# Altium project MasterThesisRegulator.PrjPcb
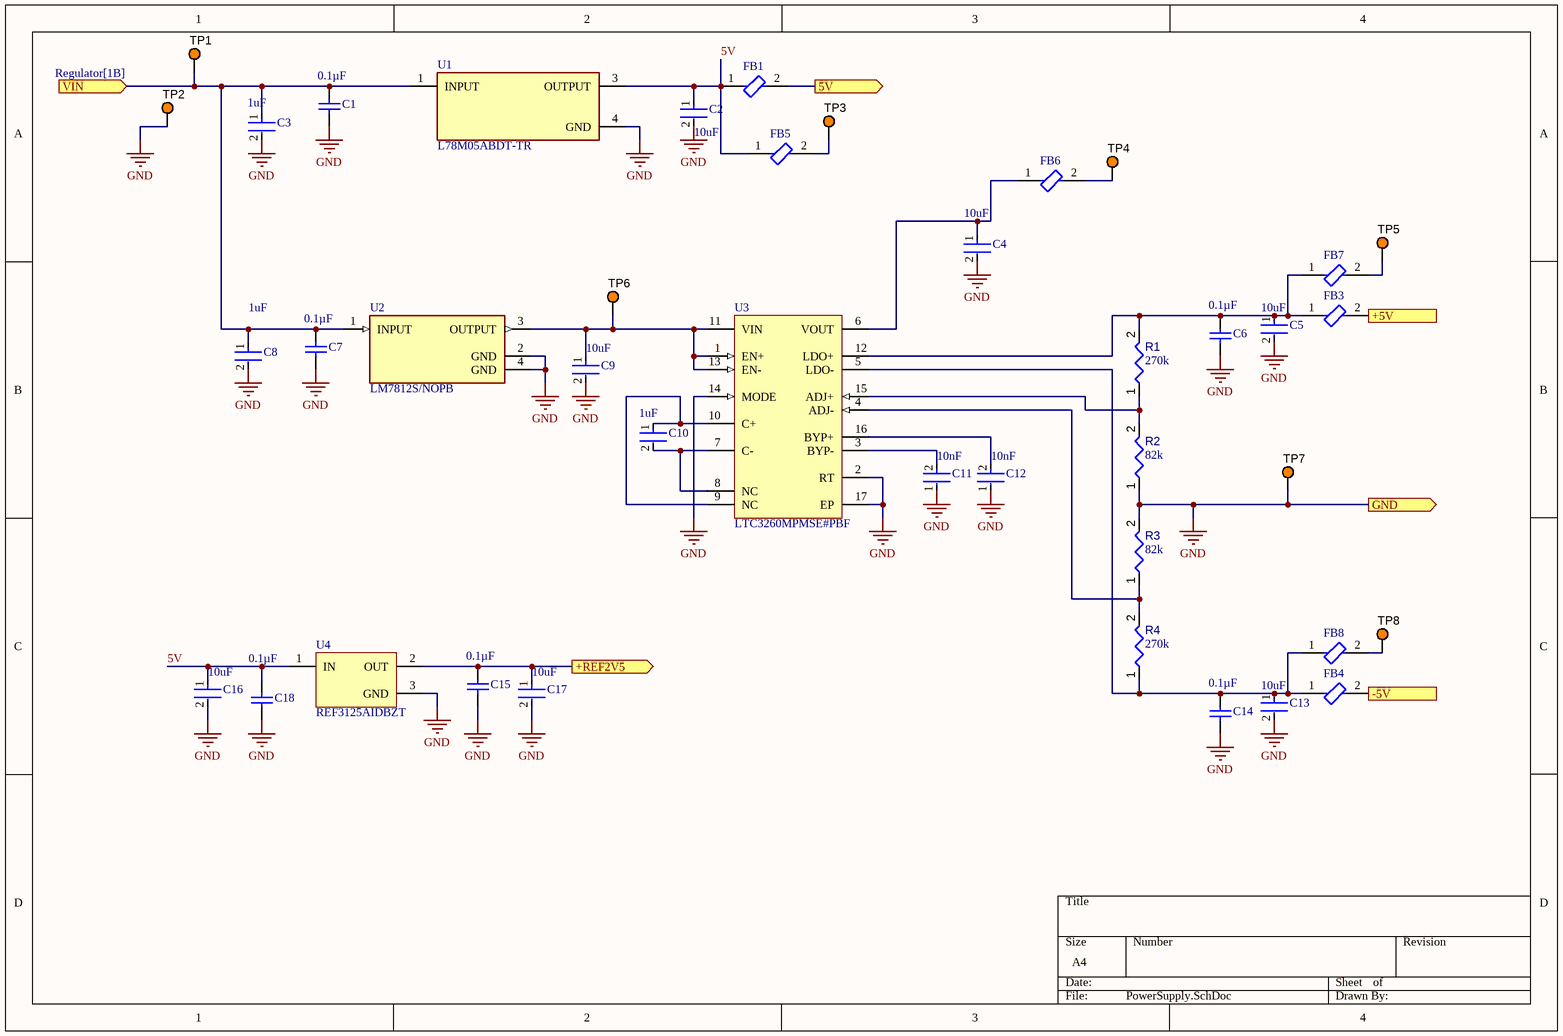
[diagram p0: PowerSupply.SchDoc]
4 sheets, 186 parts. Net scope: flat (ports and power ports of the same name join across sheets).
Board file: PCB1.PcbDoc
Sheets:
  PowerSupply.SchDoc
  Regulator.SchDoc
  ILoopAnd0.05V.SchDoc
  Support.SchDoc

## Sheet PowerSupply.SchDoc
size A4; SheetNumber: 1; SheetTotal: 5

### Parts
C1  Capacitance: 0.1µF  [SAMS-C0603-2_M]  (hidden comment: CL10B104KB8NNNC)
C2  value 10uF  [FP-CL31B106KBHNNNE-MFG]  (hidden comment: CL31B106KBHNNNE)
C3  Capacitance: 1uF  [FP-CL21-IPC_C]  (hidden comment: CL21B105KBFNNNG)
C4  value 10uF  [FP-CL31B106KBHNNNE-MFG]  (hidden comment: CL31B106KBHNNNE)
C5  value 10uF  [FP-CL31B106KBHNNNE-MFG]  (hidden comment: CL31B106KBHNNNE)
C6  Capacitance: 0.1µF  [SAMS-C0603-2_M]  (hidden comment: CL10B104KB8NNNC)
C7  Capacitance: 0.1µF  [SAMS-C0603-2_M]  (hidden comment: CL10B104KB8NNNC)
C8  Capacitance: 1uF  [FP-CL21-IPC_C]  (hidden comment: CL21B105KBFNNNG)
C9  value 10uF  [FP-CL31B106KBHNNNE-MFG]  (hidden comment: CL31B106KBHNNNE)
C10  Capacitance: 1uF  [FP-0603-L_1_6_0_15-W_0_8-IPC_C]  (hidden comment: UMK107AB7105KA-T)
C11  Capacitance: 10nF  [FP-C1608-080-0_1-MFG]  (hidden comment: C1608X7R1H103M080AA)
C12  Capacitance: 10nF  [FP-C1608-080-0_1-MFG]  (hidden comment: C1608X7R1H103M080AA)
C13  value 10uF  [FP-CL31B106KBHNNNE-MFG]  (hidden comment: CL31B106KBHNNNE)
C14  Capacitance: 0.1µF  [SAMS-C0603-2_M]  (hidden comment: CL10B104KB8NNNC)
C15  Capacitance: 0.1µF  [SAMS-C0603-2_M]  (hidden comment: CL10B104KB8NNNC)
C16  value 10uF  [FP-CL31B106KBHNNNE-MFG]  (hidden comment: CL31B106KBHNNNE)
C17  value 10uF  [FP-CL31B106KBHNNNE-MFG]  (hidden comment: CL31B106KBHNNNE)
C18  Capacitance: 0.1µF  [SAMS-C0603-2_M]  (hidden comment: CL10B104KB8NNNC)
FB1  BLM18PG600SH1D  [FP-BLM18-0_15-t0_8-IPC_C]  (value not drawn)
FB3  BLM18PG600SH1D  [FP-BLM18-0_15-t0_8-IPC_C]  (value not drawn)
FB4  BLM18PG600SH1D  [FP-BLM18-0_15-t0_8-IPC_C]  (value not drawn)
FB5  BLM18PG600SH1D  [FP-BLM18-0_15-t0_8-IPC_C]  (value not drawn)
FB6  BLM18PG600SH1D  [FP-BLM18-0_15-t0_8-IPC_C]  (value not drawn)
FB7  BLM18PG600SH1D  [FP-BLM18-0_15-t0_8-IPC_C]  (value not drawn)
FB8  BLM18PG600SH1D  [FP-BLM18-0_15-t0_8-IPC_C]  (value not drawn)
R1  value 270k  [RESC0603(1608)_L]  (hidden comment: SFR03EZPJ274)
R2  value 82k  [RESC0603(1608)_L]  (hidden comment: SFR03EZPJ823)
R3  value 82k  [RESC0603(1608)_L]  (hidden comment: SFR03EZPJ823)
R4  value 270k  [RESC0603(1608)_L]  (hidden comment: SFR03EZPJ274)
TP1  5003  [KSTN-5003]  (value not drawn)
TP2  5003  [KSTN-5003]  (value not drawn)
TP3  5003  [KSTN-5003]  (value not drawn)
TP4  5003  [KSTN-5003]  (value not drawn)
TP5  5003  [KSTN-5003]  (value not drawn)
TP6  5003  [KSTN-5003]  (value not drawn)
TP7  5003  [KSTN-5003]  (value not drawn)
TP8  5003  [KSTN-5003]  (value not drawn)
U1  L78M05ABDT-TR  [FP-L78M05ABDT-TR-MFG]
U2  LM7812S/NOPB  [FP-KTT0003B-MFG]
U3  LTC3260MPMSE#PBF  [LT-MSE-16-EDP_N]
U4  REF3125AIDBZT  [DBZ0003A_M]

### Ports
5V (out, see Regulator[2D], Support[1A]), +5V (out, see ILoopAnd0.05V[2C], Regulator[2D], Support[1A]), +REF2V5 (out, see ILoopAnd0.05V[2A], Regulator[6B]), -5V (out, see ILoopAnd0.05V[2C], Regulator[2D], Support[1A]), GND (out, see ILoopAnd0.05V[2C], Regulator[2C], Support[1A]), VIN (in, see Regulator[1B])

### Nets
+5: FB1.2 FB3.2 ; port 5V, port +5V
-5: FB4.2 ; port -5V
GND: C1.1 C2.2 C3.2 C4.2 C5.2 C6.1 C7.1 C8.2 C9.2 C11.1 C12.1 C13.2 C14.1 C15.1 C16.2 C17.2 C18.1 R2.1 R3.2 TP2.1 TP7.1 U1.4(GND) U2.2(GND) U2.4(GND) U3.2(RT) U3.14(MODE) U3.17(EP) U4.3(GND) ; port GND
5V: C2.1 C16.1 C18.2 FB1.1 FB5.1 U1.3(OUTPUT) U4.1(IN)
+REF2V5: C15.2 C17.1 U4.2(OUT) ; port +REF2V5
NetC1_2: C1.2 C3.1 C7.2 C8.1 TP1.1 U1.1(INPUT) U2.1(INPUT) ; port VIN
NetC4_1: C4.1 FB6.1 U3.6(VOUT)
NetC5_1: C5.1 C6.2 FB3.1 FB7.1 R1.2 U3.12(LDO+)
NetC9_1: C9.1 TP6.1 U2.3(OUTPUT) U3.1(EN+) U3.11(VIN) U3.13(EN-)
NetC10_1: C10.1 U3.9(NC) U3.10(C+)
NetC10_2: C10.2 U3.7(C-) U3.8(NC)
NetC11_2: C11.2 U3.3(BYP-)
NetC12_2: C12.2 U3.16(BYP+)
NetC13_1: C13.1 C14.2 FB4.1 FB8.1 R4.1 U3.5(LDO-)
NetFB5_2: FB5.2 TP3.1
NetFB6_2: FB6.2 TP4.1
NetFB7_2: FB7.2 TP5.1
NetFB8_2: FB8.2 TP8.1
NetR1_1: R1.1 R2.2 U3.15(ADJ+)
NetR3_1: R3.1 R4.2 U3.4(ADJ-)

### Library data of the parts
C1 C6 C7 C14 C15 C18 = CMP-2000-05332-1: Multi-layer Ceramic Capacitor, -55 to 125 degC, 2-Pin SMD (0603), RoHS, Tape and Reel; Manufacturer: Samsung Electro-Mechanics; Rated Voltage: 50V; Dielectric: X7R; Tolerance (%): ±10%
C2 C4 C5 C9 C13 C16 C17 = CMP-2000-07530-2: CAP CER 10UF 50V X7R 1206; Manufacturer: Samsung; Tolerance: 10%; Material: Ceramic; Temperature Coefficient: 15%
C3 C8 = CMP-13271-001433-1: CL21 Series 0805 1uF 50V ±10% Tolerance X7R Multilayer Ceramic Chip Capacitor
C10 = CMP-2000-07531-4: Ceramic Capacitor General Use 1uF ±10% 50V X7R 0603
C11 C12 = CMP-08246-006703-1: Multilayer Ceramic Capacitors 10nF ±20% 50V X7R SMD 0603
FB1 FB3-FB8 = CMP-06046-002563-1: Chip Ferrite Bead, 0603, 60Ω @ 100MHz, 0.1Ω, , 1A; Max Current Rating: 500mA; Impedance: 60R; DC Resistance (DCR): 100mR; Number of Circuits: 1; Material: Steel; Tolerance: 25%; Shielding: Unshielded
R1 R4 = CMP-009-00069-1: Manufacturer: Rohm; Power: 0.1W; Tolerance: 5%
R2 R3 = CMP-009-00069-1: Power: 0.1W; Tolerance: 5%
TP1-TP8 = CMP-002-00037-1: Test Point, Orange, Height 4.6 mm, Tail Length 3 mm, 1-Pin THD, RoHS; Manufacturer: Keystone
U1 = CMP-0244-00177-2: IC REG LINEAR 5V 500MA DPAK; Polarity: Positive; Accuracy: 2%; Max Input Voltage: 35V; Tolerance: 4%; Power Supply Rejection Ratio (PSRR): 62dB; Dropout Voltage: 2V; Output Type: Fixed; Number of Regulators: 1; Min Input Voltage: 10V; Quiescent Current: 6mA
U2 = CMP-04917-000197-1: IC REG LINEAR 12V 1.5A; Quiescent Current: 8mA; Dropout Voltage: 2V
U3 = CMP-0475-00263-1: Low Noise Dual Supply Inverting Charge Pump, 4.5 to 32 V Vin, Adjustable Vout, 16-pin SOP (MSE-16-EDP), -50 to 150 degC, Pb-Free; Manufacturer: Linear Technology; Isupply(mA): 0.1; Ishutdown(uA): 2; Vin Min(V): 4.5; Voutput: Adj; Max Iout(mA): 100; Vin Max(V): 32; Frequency(kHz): 500
U4 = CMP-0367-00203-2: 20 ppm / degC Max, 100 uA Series Voltage Reference, -40 to 125 degC, 3-pin SOT-23 (DBZ), Green (RoHS & no Sb/Br); Manufacturer: Texas Instruments; Temp Coeff(Typ)(ppm/ degree C): 10; Temp Coeff(Max)(ppm/ degree C): 20; VI(Max)(V): 5.5; Iq(Max)(uA): 100; VO(V): 2.5; Initial Accuracy @ 25/deg C(%): 0.2; Rating: Catalog; VI(Min)(V): 2.55

## Sheet Regulator.SchDoc
size A3; SheetNumber: 2; SheetTotal: 5
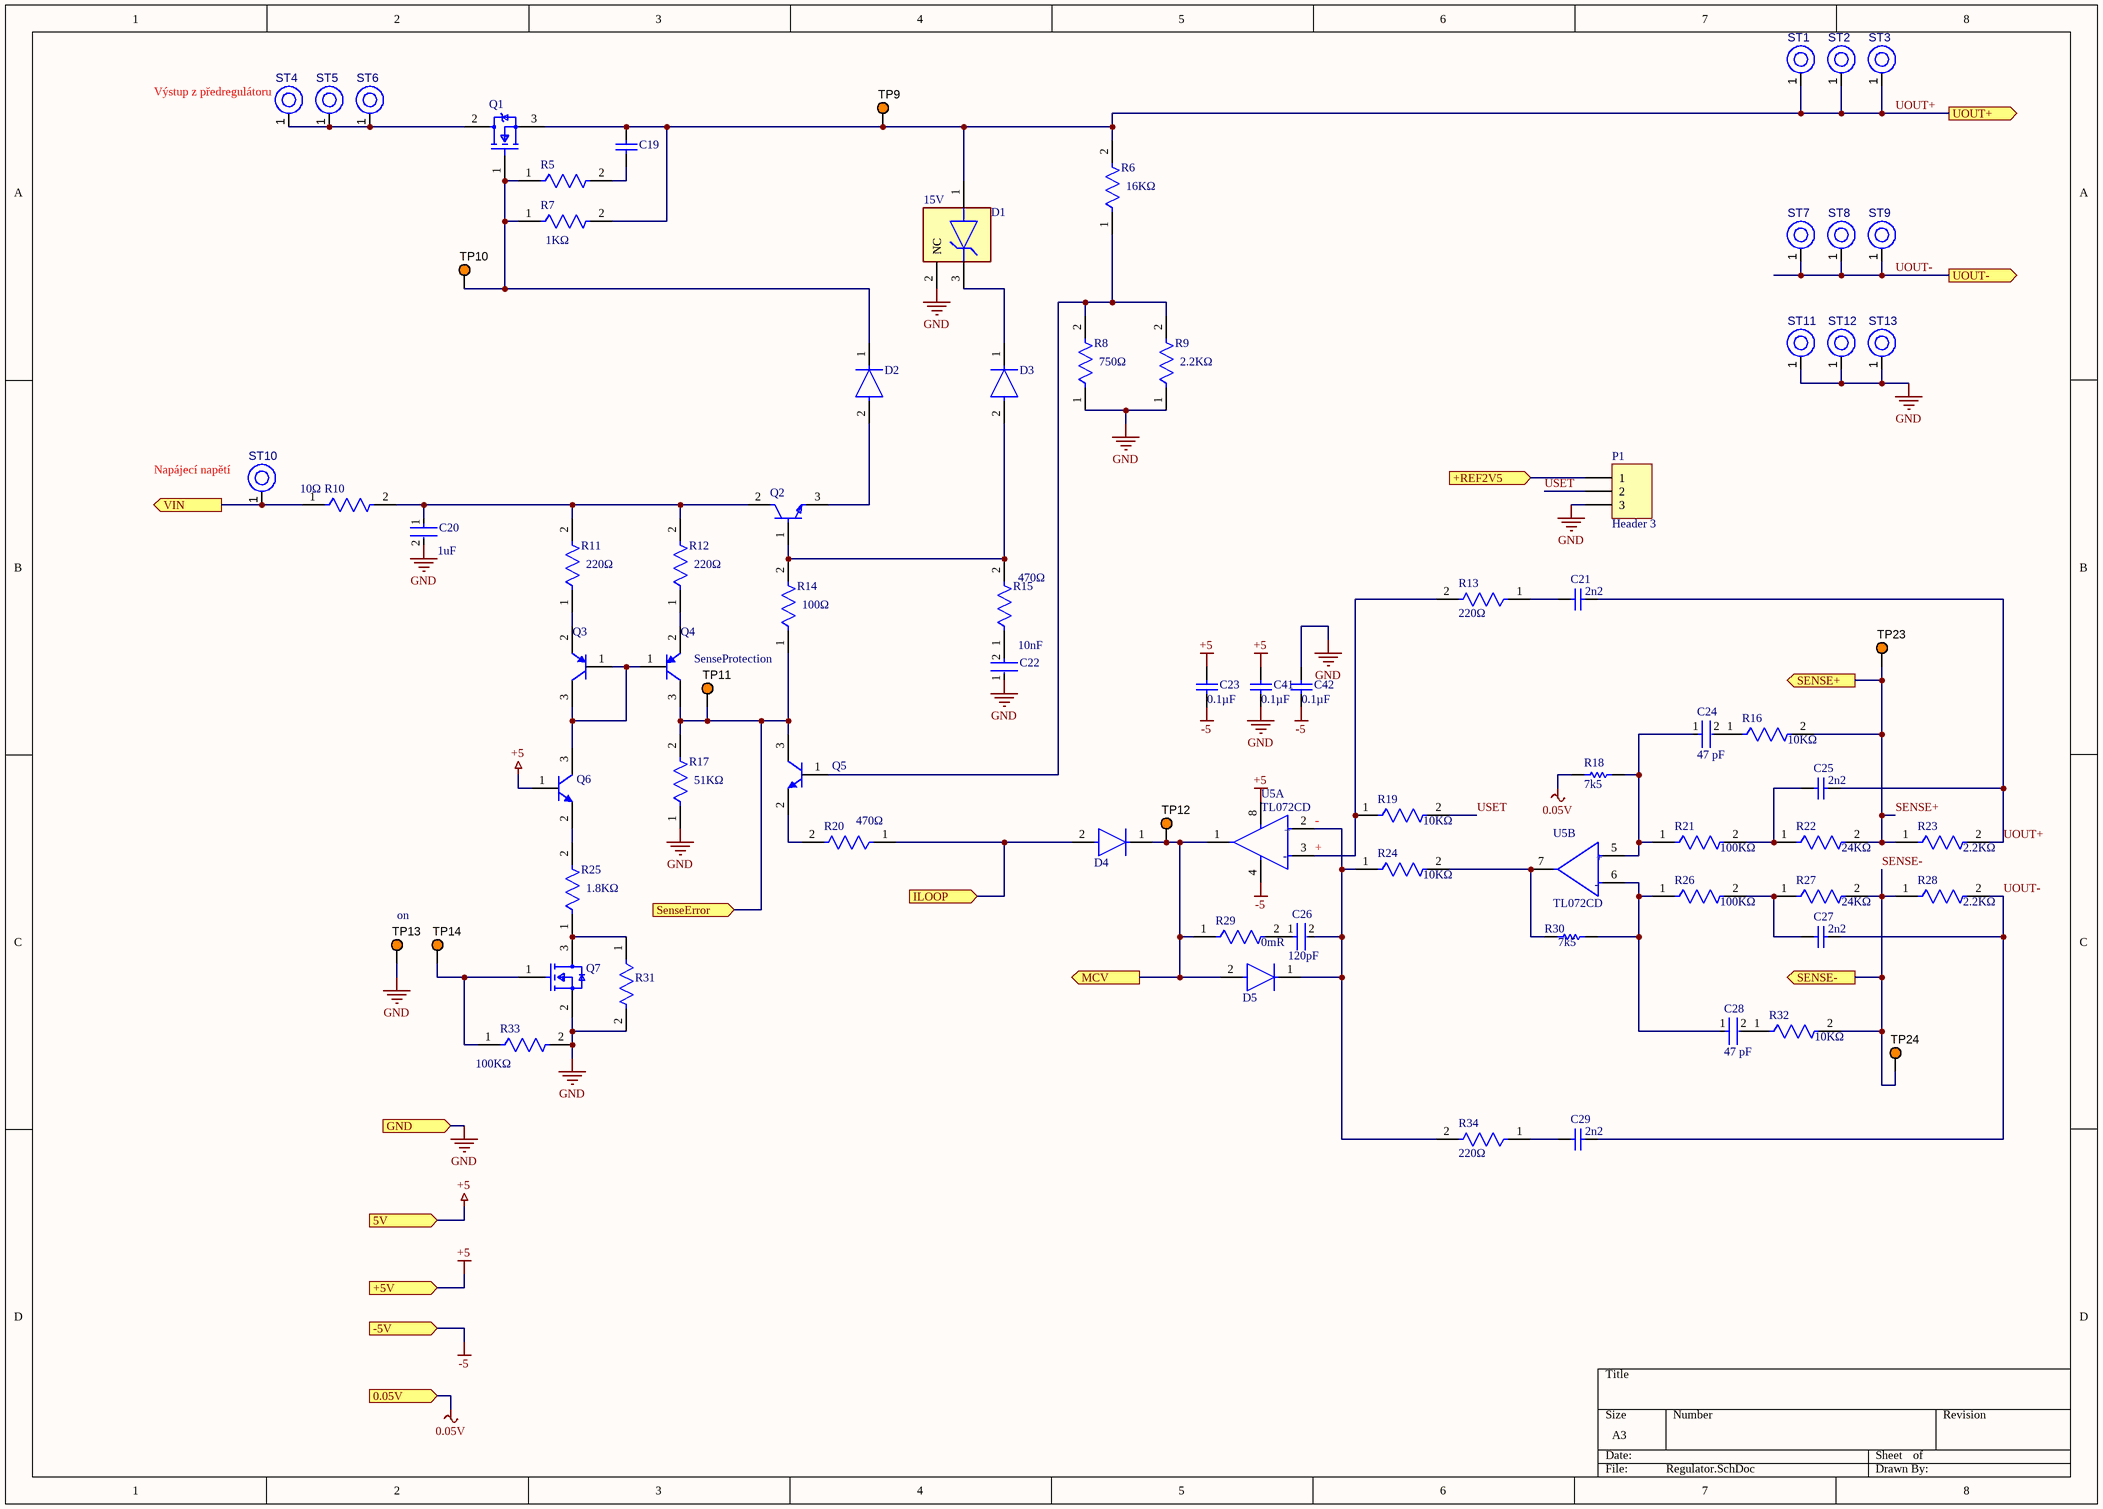
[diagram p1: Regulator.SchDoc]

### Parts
C19  CL10B104KB8NNNC  [SAMS-C0603-2_M]  (value not drawn)
C20  Capacitance: 1uF  [FP-0603-L_1_6_0_15-W_0_8-IPC_C]  (hidden comment: UMK107AB7105KA-T)
C21  value 2n2  [CAPC1608X90X35ML15T15]  (hidden comment: 06035C222KAT4A)
C22  Capacitance: 10nF  [FP-C1608-080-0_1-IPC_A]  (hidden comment: C1608X7R1H103M080AA)
C23  Capacitance: 0.1µF  [SAMS-C0603-2_M]  (hidden comment: CL10B104KB8NNNC)
C24  Capacitance: 47 pF  [FP-C0603C-CF-MFG]  (hidden comment: C0603C470M5HACTU)
C25  value 2n2  [CAPC1608X90X35ML15T15]  (hidden comment: 06035C222KAT4A)
C26  Capacitance: 120pF  [FP-CL10-IPC_A]  (hidden comment: CL10B121KB8NNNC)
C27  value 2n2  [CAPC1608X90X35ML15T15]  (hidden comment: 06035C222KAT4A)
C28  Capacitance: 47 pF  [FP-C0603C-CF-MFG]  (hidden comment: C0603C470M5HACTU)
C29  value 2n2  [CAPC1608X90X35ML15T15]  (hidden comment: 06035C222KAT4A)
C41  Capacitance: 0.1µF  [SAMS-C0603-2_M]  (hidden comment: CL10B104KB8NNNC)
C42  Capacitance: 0.1µF  [SAMS-C0603-2_M]  (hidden comment: CL10B104KB8NNNC)
D1  BZX84-C15,215  [FP-SOT23-MFG]  (value not drawn)
D2  BAS316,115  [FP-SOD323-IPC_A]  (value not drawn)
D3  BAS316,115  [FP-SOD323-IPC_A]  (value not drawn)
D4  BAS316,115  [FP-SOD323-IPC_A]  (value not drawn)
D5  BAS316,115  [FP-SOD323-IPC_A]  (value not drawn)
P1  Header 3  [HDR1X3]
Q1  IRFP250NPBF  [FP-PG-TO247-3-MFG]  (value not drawn)
Q2  BCP56-16  [FP-SOT-223-P008-MFG]  (value not drawn)
Q3  MMBT5401LT1G  [ONSC-SOT-23-3-318-08_V]  (value not drawn)
Q4  MMBT5401LT1G  [ONSC-SOT-23-3-318-08_V]  (value not drawn)
Q5  MMBT5551LT1G  [ONSC-SOT-23-3-318-08_V]  (value not drawn)
Q6  MMBT5551LT1G  [ONSC-SOT-23-3-318-08_V]  (value not drawn)
Q7  2N7002-7-F  [FP-SOT23-MFG]  (value not drawn)
R5  RT0603FRE0710KL  [FP-RT0603-MFG]  (value not drawn)
R6  Resistance: 16KΩ  [FP-RT0603-MFG]  (hidden comment: RT0603DRE0716KL)
R7  Resistance: 1KΩ  [FP-RT0603-MFG]  (hidden comment: RT0603FRE071KL)
R8  Resistance: 750Ω  [FP-RT0603-MFG]  (hidden comment: RT0603DRE07750RL)
R9  Resistance: 2.2KΩ  [FP-RT0603-MFG]  (hidden comment: RT0603FRE072K2L)
R10  Resistance: 10Ω  [FP-RT0603-MFG]  (hidden comment: RT0603FRE0710RL)
R11  Resistance: 220Ω  [FP-RT0603-MFG]  (hidden comment: RT0603FRE07220RL)
R12  Resistance: 220Ω  [FP-RT0603-MFG]  (hidden comment: RT0603FRE07220RL)
R13  Resistance: 220Ω  [FP-RT0603-MFG]  (hidden comment: RT0603FRE07220RL)
R14  Resistance: 100Ω  [FP-RT0603-MFG]  (hidden comment: RT0603FRE07100RL)
R15  value 470Ω  [FP-RT0603-MFG]  (hidden comment: RT0603FRE07470RL)
R16  Resistance: 10KΩ  [FP-RT0603-MFG]  (hidden comment: RT0603FRE0710KL)
R17  Resistance: 51KΩ  [FP-RT0603-MFG]  (hidden comment: RT0603FRE0751KL)
R18  value 7k5  [RESC1608X55X30ML20T20]  (hidden comment: ERA3AEB752V)
R19  Resistance: 10KΩ  [FP-RT0603-MFG]  (hidden comment: RT0603FRE0710KL)
R20  value 470Ω  [FP-RT0603-MFG]  (hidden comment: RT0603FRE07470RL)
R21  value 100KΩ  [FP-RT0603-MFG]  (hidden comment: RT0603BRD07100KL)
R22  Resistance: 24KΩ  [FP-RT0603-MFG]  (hidden comment: RT0603BRD0724KL)
R23  Resistance: 2.2KΩ  [FP-RT0603-MFG]  (hidden comment: RT0603BRD072K2L)
R24  Resistance: 10KΩ  [FP-RT0603-MFG]  (hidden comment: RT0603FRE0710KL)
R25  Resistance: 1.8KΩ  [FP-RT0603-MFG]  (hidden comment: RT0603FRE071K8L)
R26  Resistance: 100KΩ  [FP-RT0603-MFG]  (hidden comment: RT0603BRD07100KL)
R27  Resistance: 24KΩ  [FP-RT0603-MFG]  (hidden comment: RT0603BRD0724KL)
R28  Resistance: 2.2KΩ  [FP-RT0603-MFG]  (hidden comment: RT0603BRD072K2L)
R29  Resistance: 0mR  [FP-CRG0603-IPC_C]  (hidden comment: CRG0603ZR)
R30  value 7k5  [RESC1608X55X30ML20T20]  (hidden comment: ERA3AEB752V)
R31  0R  [FP-RT0603-MFG]  (value not drawn)
R32  Resistance: 10KΩ  [FP-RT0603-MFG]  (hidden comment: RT0603FRE0710KL)
R33  Resistance: 100KΩ  [FP-RT0603-MFG]  (hidden comment: RT0603FRE07100KL)
R34  Resistance: 220Ω  [FP-RT0603-MFG]  (hidden comment: RT0603FRE07220RL)
ST1  PTH-M2D5X5  [PTH-M2D5X5]  (value not drawn)
ST2  PTH-M2D5X5  [PTH-M2D5X5]  (value not drawn)
ST3  PTH-M2D5X5  [PTH-M2D5X5]  (value not drawn)
ST4  PTH-M2D5X5  [PTH-M2D5X5]  (value not drawn)
ST5  PTH-M2D5X5  [PTH-M2D5X5]  (value not drawn)
ST6  PTH-M2D5X5  [PTH-M2D5X5]  (value not drawn)
ST7  PTH-M2D5X5  [PTH-M2D5X5]  (value not drawn)
ST8  PTH-M2D5X5  [PTH-M2D5X5]  (value not drawn)
ST9  PTH-M2D5X5  [PTH-M2D5X5]  (value not drawn)
ST10  PTH-M2D5X5  [PTH-M2D5X5]  (value not drawn)
ST11  PTH-M2D5X5  [PTH-M2D5X5]  (value not drawn)
ST12  PTH-M2D5X5  [PTH-M2D5X5]  (value not drawn)
ST13  PTH-M2D5X5  [PTH-M2D5X5]  (value not drawn)
TP9  5003  [KSTN-5003]  (value not drawn)
TP10  5003  [KSTN-5003]  (value not drawn)
TP11  5003  [KSTN-5003]  (value not drawn)
TP12  5003  [KSTN-5003]  (value not drawn)
TP13  5003  [KSTN-5003]  (value not drawn)
TP14  5003  [KSTN-5003]  (value not drawn)
TP23  5003  [KSTN-5003]  (value not drawn)
TP24  5003  [KSTN-5003]  (value not drawn)
U5  TL072CD  [FP-SO8-IPC_C]  (parts A,B of 2)

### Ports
0.05V (in, see ILoopAnd0.05V[2A]), 5V (in, see PowerSupply[3A], Support[1A]), +5V (in, see ILoopAnd0.05V[2C], PowerSupply[4B], Support[1A]), +REF2V5 (in, see ILoopAnd0.05V[2A], PowerSupply[2C]), -5V (in, see ILoopAnd0.05V[2C], PowerSupply[4C], Support[1A]), GND (in, see ILoopAnd0.05V[2C], PowerSupply[4B], Support[1A]), ILOOP (in, see ILoopAnd0.05V[2B]), MCV (out, see Support[2A]), SENSE+ (out, see Support[8B]), SENSE- (out, see Support[8C]), SenseError (in, see Support[5B]), UOUT+ (out, see Support[8B]), UOUT- (out, see ILoopAnd0.05V[7B], Support[8C]), VIN (out, see PowerSupply[1A])

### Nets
0.05V: R18.2 ; port 0.05V
+5: C23.2 C41.2 Q6.1(B) U5.8(VCC+) ; port 5V, port +5V
-5: C23.1 C42.1 U5.4(VCC-) ; port -5V
GND: C20.2 C22.1 C41.1 C42.2 D1.2(NC) P1.3 Q7.2(S) R8.1 R9.1 R17.1 R31.2 R33.2 ST11.1(H1) ST12.1(H1) ST13.1(H1) TP13.1 ; port GND
+REF2V5: P1.1 ; port +REF2V5
SENSE+: R16.2 R22.2 R23.1 TP23.1 ; port SENSE+
SENSE-: R27.2 R28.1 R32.2 TP24.1 ; port SENSE-
UOUT+: C19.2 C21.2 C25.2 D1.1(A) Q1.3(SOURCE) R6.2 R7.2 R23.2 ST1.1(H1) ST2.1(H1) ST3.1(H1) TP9.1 ; port UOUT+
UOUT-: C27.2 C29.2 R28.2 ST7.1(H1) ST8.1(H1) ST9.1(H1) ; port UOUT-
USET: P1.2 R19.2
NetC1_2: R10.1 ST10.1(H1) ; port VIN
NetC19_1: C19.1 R5.2
NetC20_1: C20.1 Q2.2(C) R10.2 R11.2 R12.2
NetC21_1: C21.1 R13.1
NetC22_2: C22.2 R15.1
NetC24_1: C24.1 R18.1 R21.1 U5.5(Non-inverting_input_2)
NetC24_2: C24.2 R16.1
NetC25_1: C25.1 R21.2 R22.1
NetC26_1: C26.1 R29.2
NetC26_2: C26.2 D5.1(C) R24.1 R34.2 U5.2(Inverting_input_1)
NetC27_1: C27.1 R26.2 R27.1
NetC28_1: C28.1 R26.1 R30.2 U5.6(Inverting_input_2)
NetC28_2: C28.2 R32.1
NetC29_1: C29.1 R34.1
NetD1_3: D1.3(C) D3.1(C)
NetD2_1: D2.1(C) Q1.1(GATE) R5.1 R7.1 TP10.1
NetD2_2: D2.2(A) Q2.3(E)
NetD3_2: D3.2(A) Q2.1(B) R14.2 R15.2
NetD4_1: D4.1(C) D5.2(A) R29.1 TP12.1 U5.1(Output_1) ; port MCV
NetD4_2: D4.2(A) R20.1 ; port ILOOP
NetQ1_2: Q1.2(DRAIN) ST4.1(H1) ST5.1(H1) ST6.1(H1)
NetQ3_1: Q3.1(B) Q3.3(C) Q4.1(B) Q6.3(C)
NetQ3_2: Q3.2(E) R11.1
NetQ4_2: Q4.2(E) R12.1
NetQ4_3: Q4.3(C) Q5.3(C) R14.1 R17.2 TP11.1 ; port SenseError
NetQ5_1: Q5.1(B) R6.1 R8.2 R9.2
NetQ5_2: Q5.2(E) R20.2
NetQ6_2: Q6.2(E) R25.2
NetQ7_1: Q7.1(G) R33.1 TP14.1
NetQ7_3: Q7.3(D) R25.1 R31.1
NetR13_2: R13.2 R19.1 U5.3(Non-inverting_input_1)
NetR24_2: R24.2 R30.1 U5.7(Output_2)

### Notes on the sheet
- (near ST4) Výstup z předregulátoru
- (near D1) 15V
- (near ST10) Napájecí napětí
- (near Q4) SenseProtection
- (near U5) -
- (near U5) +
- on

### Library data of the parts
C19 = CMP-2000-05332-1: Multi-layer Ceramic Capacitor, -55 to 125 degC, 2-Pin SMD (0603), RoHS, Tape and Reel; Manufacturer: Samsung Electro-Mechanics; Capacitance: 0.1µF; Rated Voltage: 50V; Dielectric: X7R; Tolerance (%): ±10%
C20 = CMP-2000-07531-4: as C10 on sheet PowerSupply
C21 C25 C27 C29 = CMP-2006-04410-1: Manufacturer: AVX Interconnect / Elco
C22 = CMP-08246-006703-1: as C11 on sheet PowerSupply
C23 C41 C42 = CMP-2000-05332-1: as C1 on sheet PowerSupply
C24 C28 = CMP-03020-010187-1: C0603 47 pF X8R 30ppm/°C 20.00% 50 V; Manufacturer: KEMET; Material: Ceramic; Value: 47 pF; Tolerance: 0.2; Automotive Grade: Grade 1; Voltage Rating: 50 V
C26 = CMP-13271-001091-1: Cap Ceramic 120pF 50V X7R ±10% Pad SMD 0603 +125°C T/R
D1 = CMP-14400-000028-1: DIODE ZENER 15V 250MW TO236AB
D2-D5 = CMP-14399-000012-1: DIODE GEN PURP 100V 250MA SOD323
P1 = Header 3: Header, 3-Pin
Q1 = CMP-32901-000198-1: MOSFET N-CH 200V 30A TO-247AC; Rds On Max: 75mR; Input Capacitance: 2.159nF; Turn-Off Delay Time: 41ns; Max Power Dissipation: 214W; Turn-On Delay Time: 14ns; Gate to Source Voltage (Vgs): 20V; Element Configuration: Single
Q2 = CMP-12195-000003-1: TRANS NPN 80V 1A SOT-223; Manufacturer: STMicroelectronics; Number Of Npn: 1; Hfe Max: 250; Hfe Min: 100; Power Dissipation: 1.6W; Collector Base Voltage: 100V; Emitter Base Voltage: 5V; Max Junction Temp: +150°C; Rthja Max: 78°C/W; Standoff Height: 0.02mm; Collector Emitter Saturation Voltage: 0.5V; Hfe Testvce: 2V; Hfe Testic: 150mA
Q3 Q4 = CMP-1048-00557-1: High Voltage Transistor, PNP Silicon, 3-Pin SOT-23, Pb-Free, Tape and Reel; Manufacturer: On Semiconductor; fT Min (MHz): 100; IC Continuous (A): -0.5
Q5 Q6 = CMP-1048-00669-1: High Voltage Transistor, NPN Silicon, 3-Pin SOT-23, Pb-Free, Tape and Reel; Manufacturer: On Semiconductor; IC Continuous (A): 0.6
Q7 = CMP-2000-04929-2: MOSFET N-CH 60V 115MA SOT23-3; Turn-On Delay Time: 7ns; Turn-Off Delay Time: 11ns; Drain to Source Resistance: 7.5R; Rise Time: 3ns; Drain to Source Breakdown Voltage: 70V; Input Capacitance: 50pF; Number of Elements: 1; Power Dissipation: 540mW; Max Power Dissipation: 300mW; Fall Time: 5.6ns; Gate to Source Voltage (Vgs): 20V; Threshold Voltage: 2.5V; Element Configuration: Single
R5 R16 R19 R24 R32 = CMP-03412-005349-1: RES SMD 10K OHM 1% 1/10W 0603; Manufacturer: Yageo; Value: 10KΩ; Temperature Coefficient: 50 ppm/°C; Power Rating: 0.1W; Tolerance: 0.01; Voltage Rating: 75V
R6 = CMP-03412-013381-1: RES 16.0K OHM 1/10W .5% SMD 0603; Manufacturer: Yageo; Voltage Rating: 75V; Value: 16KΩ; Temperature Coefficient: 50 ppm/°C; Power Rating: 0.1W; Tolerance: 0.005
R7 = CMP-03412-005349-1: RES SMD 1K OHM 1% 1/10W 0603 Je tuspatny datasheet!!!; Manufacturer: Yageo; Manufacturer Part Number: RT0603FRE0710KL; Value: 1KΩ; Temperature Coefficient: 50 ppm/°C; Power Rating: 0.1W; Tolerance: 0.01; Voltage Rating: 75V; Max Power Dissipation: 100mW
R8 = CMP-2000-04630-2: RES SMD 750 OHM 0.5% 1/10W 0603; Manufacturer: Yageo; Tolerance: 0.005; Power Rating: 0.1W; Voltage Rating: 75V; Temperature Coefficient: 50 ppm/°C; Value: 750Ω
R9 = CMP-03412-033768-1: RES SMD 2.2K OHM 1% 1/10W 0603; Manufacturer: Yageo; Temperature Coefficient: 50 ppm/°C; Power Rating: 0.1W; Value: 2.2KΩ; Tolerance: 0.01; Voltage Rating: 75V
R10 = CMP-03412-033408-1: RES SMD 10 OHM 1% 1/10W 0603; Manufacturer: Yageo; Voltage Rating: 75V; Power Rating: 0.1W; Temperature Coefficient: 50 ppm/°C; Tolerance: 0.01; Value: 10Ω
R11-R13 R34 = CMP-03412-006815-1: RES SMD 220 OHM 1% 1/10W 0603; Manufacturer: Yageo; Temperature Coefficient: 50 ppm/°C; Tolerance: 0.01; Power Rating: 0.1W; Voltage Rating: 75V; Value: 220Ω
R14 = CMP-03412-022806-1: RES SMD 100 OHM 1% 1/10W 0603; Manufacturer: Yageo; Value: 100Ω; Power Rating: 0.1W; Voltage Rating: 75V; Temperature Coefficient: 50 ppm/°C; Tolerance: 0.01
R15 R20 = CMP-03412-035774-1: RES 470 OHM 1/10W 1% SMD 0603; Manufacturer: Yageo; Power Rating: 0.1W; Tolerance: 0.01; Temperature Coefficient: 50 ppm/°C; Voltage Rating: 75V
R17 = CMP-2000-04770-2: RES SMD 51K OHM 1% 1/10W 0603; Manufacturer: Yageo; Temperature Coefficient: 50 ppm/°C; Value: 51KΩ; Voltage Rating: 75V; Tolerance: 0.01; Power Rating: 0.1W
R18 R30 = CMP-2000-00123-1: Manufacturer: Panasonic
R21 = CMP-2000-04343-2: RES 100K OHM 1/10W .1% SMD 0603; Manufacturer: Yageo; Voltage Rating: 75V; Power Rating: 0.1W; Temperature Coefficient: 25 ppm/°C; Tolerance: 0.001
R22 R27 = CMP-2000-04411-2: RES 24.0K OHM 1/10W .1% SMD 0603; Manufacturer: Yageo; Value: 24KΩ; Temperature Coefficient: 25 ppm/°C; Tolerance: 0.001; Voltage Rating: 75V; Power Rating: 0.1W
R23 R28 = CMP-2000-04423-2: RES 2.20K OHM 1/10W .1% SMD 0603; Manufacturer: Yageo; Power Rating: 0.1W; Tolerance: 0.001; Value: 2.2KΩ; Voltage Rating: 75V; Temperature Coefficient: 25 ppm/°C
R25 = CMP-03412-026125-1: RES SMD 1.8K OHM 1% 1/10W 0603; Manufacturer: Yageo; Temperature Coefficient: 50 ppm/°C; Value: 1.8KΩ; Voltage Rating: 75V; Tolerance: 0.01; Power Rating: 0.1W
R26 = CMP-2000-04343-2: RES 100K OHM 1/10W .1% SMD 0603; Manufacturer: Yageo; Voltage Rating: 75V; Power Rating: 0.1W; Temperature Coefficient: 25 ppm/°C; Value: 100KΩ; Tolerance: 0.001
R29 = CMP-03211-011415-1: RES SMD 0 OHM JUMPER 1/10W 0603; Voltage Rating: 50V; Power Rating: 100mW; Number of Resistors: 1; Tolerance: 0%; Temperature Coefficient: 100ppm/°C
R31 = CMP-03412-005349-1: Manufacturer: Yageo; Manufacturer Part Number: RT0603FRE0710KL; Temperature Coefficient: 50 ppm/°C; Power Rating: 0.1W; Tolerance: 0.01; Voltage Rating: 75V
R33 = CMP-03412-015060-1: RES SMD 100K OHM 1% 1/10W 0603; Manufacturer: Yageo; Tolerance: 0.01; Temperature Coefficient: 50 ppm/°C; Value: 100KΩ; Power Rating: 0.1W; Voltage Rating: 75V
ST1-ST13 = CMP-00028-00004-1: M2 PTH (2.5mm), 5mm pad
TP9-TP14 TP23 TP24 = CMP-002-00037-1: as TP1 on sheet PowerSupply
U5 = CMP-12131-000015-1: IC OPAMP JFET 2 CIRCUIT 8SO; Unity Gain Bandwidth Product: 4MHz; Max Supply Voltage: 36V; Max Dual Supply Voltage: 18V; Voltage Gain: 106.02dB; Output Current: 40mA; Input Offset Voltage (Vos): 10mV; Slew Rate-Nom: 13V/µs; Min Input Voltage: -12V; Number of Channels: 2; Common Mode Rejection Ratio: 70dB; Dual Supply Voltage: 15V; Supply Current: 2.5mA; Input Offset Voltage-Max: 3mV; Slew Rate: 16V/µs; Min Dual Supply Voltage: 3V; Amplifier Type: LOW NOISE; Operating Supply Current: 1.4mA; Input Bias Current: 200pA

## Sheet ILoopAnd0.05V.SchDoc
size A3; SheetNumber: 3; SheetTotal: 5
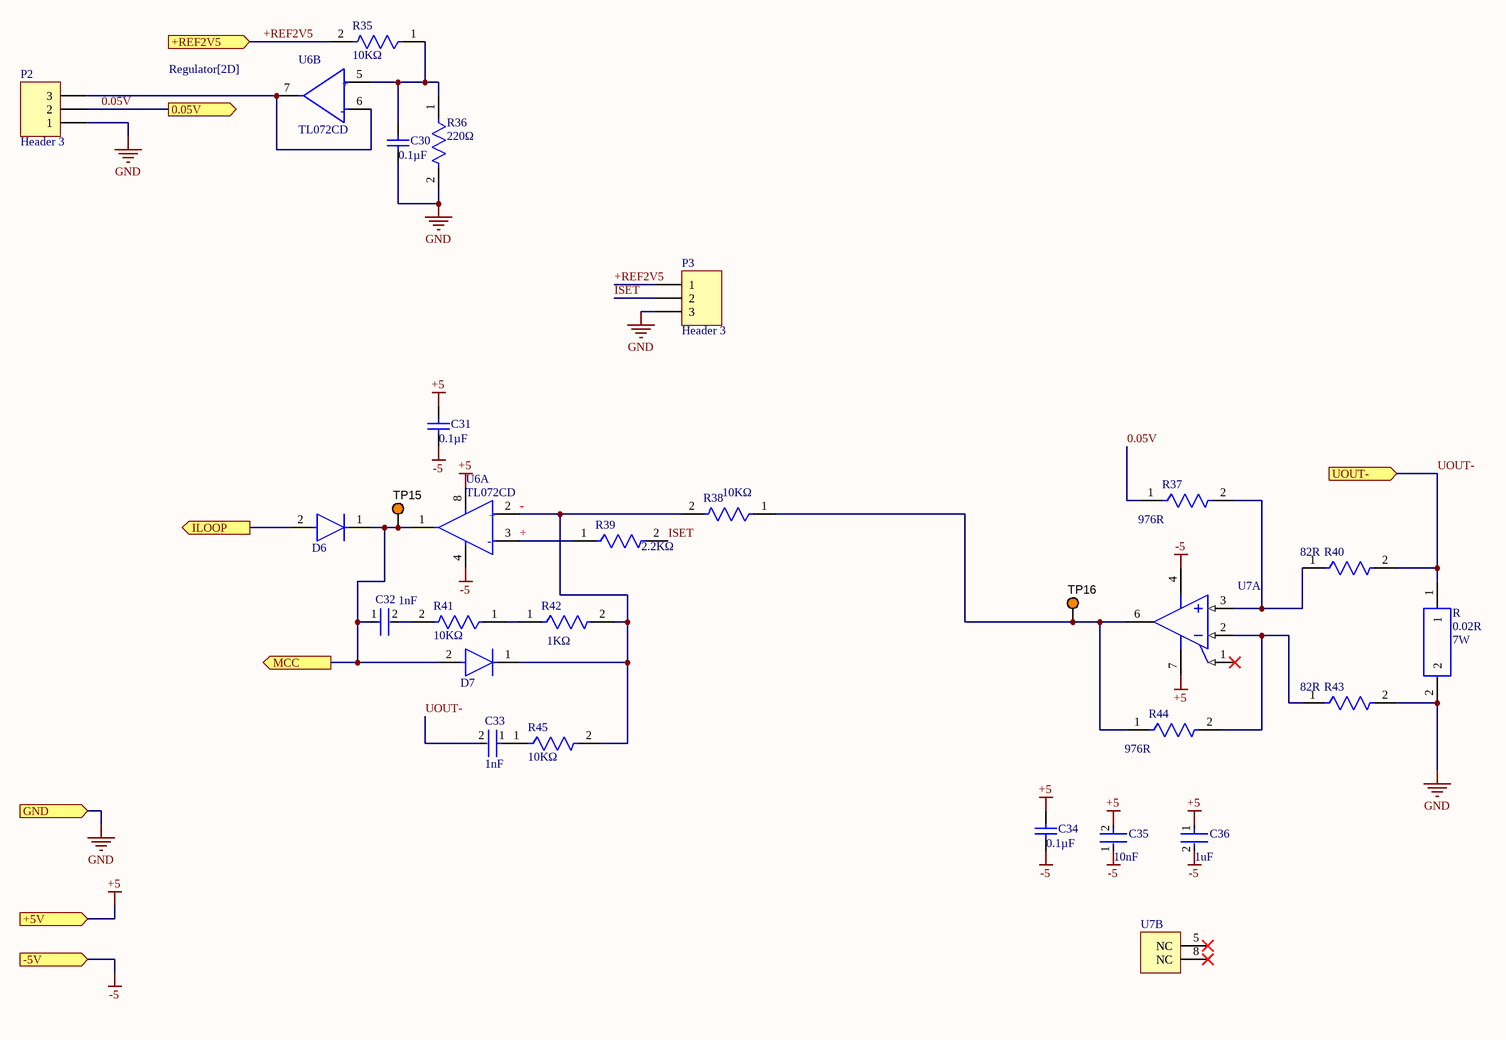
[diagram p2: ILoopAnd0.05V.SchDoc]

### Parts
C30  Capacitance: 0.1µF  [SAMS-C0603-2_M]  (hidden comment: CL10B104KB8NNNC)
C31  Capacitance: 0.1µF  [SAMS-C0603-2_M]  (hidden comment: CL10B104KB8NNNC)
C32  Capacitance: 1nF  [FP-CL10-IPC_C]  (hidden comment: CL10B102KB8WPNC)
C33  Capacitance: 1nF  [FP-CL10-IPC_C]  (hidden comment: CL10B102KB8WPNC)
C34  Capacitance: 0.1µF  [SAMS-C0603-2_M]  (hidden comment: CL10B104KB8NNNC)
C35  Capacitance: 10nF  [FP-C1608-080-0_1-IPC_A]  (hidden comment: C1608X7R1H103M080AA)
C36  Capacitance: 1uF  [FP-0603-L_1_6_0_15-W_0_8-IPC_C]  (hidden comment: UMK107AB7105KA-T)
D6  BAS316,115  [FP-SOD323-IPC_A]  (value not drawn)
D7  BAS316,115  [FP-SOD323-IPC_A]  (value not drawn)
P2  Header 3  [HDR1X3]
P3  Header 3  [HDR1X3]
R  value 0.02R  Power: 7W  [WSHM2818R0200FEA]  (hidden comment: WSHM2818R0200FEA)
R35  Resistance: 10KΩ  [FP-RT0603-MFG]  (hidden comment: RT0603FRE0710KL)
R36  Resistance: 220Ω  [FP-RT0603-MFG]  (hidden comment: RT0603FRE07220RL)
R37  Resistance: 976R  [FP-AC0603-MFG]  (hidden comment: AC0603FR-07976RL)
R38  Resistance: 10KΩ  [FP-RT0603-MFG]  (hidden comment: RT0603FRE0710KL)
R39  Resistance: 2.2KΩ  [FP-RT0603-MFG]  (hidden comment: RT0603BRD072K2L)
R40  Resistance: 82R  [FP-CRCW0603-e3-IPC_C]  (hidden comment: CRCW060382R0FKEA)
R41  Resistance: 10KΩ  [FP-RT0603-MFG]  (hidden comment: RT0603FRE0710KL)
R42  Resistance: 1KΩ  [FP-RT0603-MFG]  (hidden comment: RT0603FRE071KL)
R43  Resistance: 82R  [FP-CRCW0603-e3-IPC_C]  (hidden comment: CRCW060382R0FKEA)
R44  Resistance: 976R  [FP-AC0603-MFG]  (hidden comment: AC0603FR-07976RL)
R45  Resistance: 10KΩ  [FP-RT0603-MFG]  (hidden comment: RT0603FRE0710KL)
TP15  5003  [KSTN-5003]  (value not drawn)
TP16  5003  [KSTN-5003]  (value not drawn)
U6  TL072CD  [FP-SO8-IPC_C]  (parts A,B of 2)
U7  LTC2050HVCS8#PBF  [LT-S8-8_L]  (value not drawn)  (parts A,B of 2)

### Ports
0.05V (out, see Regulator[2D]), +5V (in, see PowerSupply[4B], Regulator[2D], Support[1A]), +REF2V5 (in, see PowerSupply[2C], Regulator[6B]), -5V (in, see PowerSupply[4C], Regulator[2D], Support[1A]), GND (in, see PowerSupply[4B], Regulator[2C], Support[1A]), ILOOP (out, see Regulator[4C]), MCC (out, see Support[2D]), UOUT- (in, see Regulator[8A], Support[8C])

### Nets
0.05V: P2.2 R37.1 ; port 0.05V
+5: C31.2 C34.2 C35.2 C36.1 U6.8(VCC+) U7.7(V+) ; port +5V
-5: C31.1 C34.1 C35.1 C36.2 U6.4(VCC-) U7.4(V-) ; port -5V
GND: C30.1 P2.1 P3.3 R.2 R36.2 R43.2 ; port GND
+REF2V5: P3.1 R35.2 ; port +REF2V5
ISET: P3.2 R39.2
UOUT-: C33.2 R.1 R40.2 ; port UOUT-
NetC30_2: C30.2 R35.1 R36.1 U6.5(Non-inverting_input_2)
NetC32_1: C32.1 D6.1(C) D7.2(A) TP15.1 U6.1(Output_1) ; port MCC
NetC32_2: C32.2 R41.2
NetC33_1: C33.1 R45.1
NetD4_2: D6.2(A) ; port ILOOP
NetD7_1: D7.1(C) R38.2 R42.2 R45.2 U6.2(Inverting_input_1)
NetP2_3: P2.3 U6.6(Inverting_input_2) U6.7(Output_2)
NetR37_2: R37.2 R40.1 U7.3(+IN)
NetR38_1: R38.1 R44.1 TP16.1 U7.6(OUT)
NetR39_1: R39.1 U6.3(Non-inverting_input_1)
NetR41_1: R41.1 R42.1
NetR43_1: R43.1 R44.2 U7.2(-IN)

Not connected (* = marked no-connect by the designer): U7 1(~{SHDN})* 5(NC)* 8(NC)*

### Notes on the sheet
- (near U6) -
- (near U6) +

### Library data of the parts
C30 C31 C34 = CMP-2000-05332-1: as C1 on sheet PowerSupply
C32 C33 = CMP-13271-004548-1: Cap Ceramic 1nF 50V X7R ±10% Pad SMD 0603 +125°C T/R
C35 = CMP-08246-006703-1: as C11 on sheet PowerSupply
C36 = CMP-2000-07531-4: as C10 on sheet PowerSupply
D6 D7 = CMP-14399-000012-1: DIODE GEN PURP 100V 250MA SOD323
P2 P3 = Header 3: Header, 3-Pin
R = WSHM2818R0200FEA: Rezistory ke snímání proudu - SMD .02ohms 7watt 1%
R35 R38 R41 R45 = CMP-03412-005349-1: as R5 on sheet Regulator
R36 = CMP-03412-006815-1: as R11 on sheet Regulator
R37 R44 = CMP-03412-004734-2: RES 976Ω 1.00% 0.1W 0603; Voltage Rating: 50V; Max Power Dissipation: 100mW; Temperature Coefficient: 100ppm/°C; Tolerance: 1%
R39 = CMP-2000-04423-2: as R23 on sheet Regulator
R40 R43 = CMP-2000-03606-2: RES Thick Film, 82Ω, 1%, 0.1W, 100ppm/°C, 0603; Power Rating: 100mW; Voltage Rating (DC): 75V
R42 = CMP-03412-005349-1: as R7 on sheet Regulator
TP15 TP16 = CMP-002-00037-1: as TP1 on sheet PowerSupply
U6 = CMP-12131-000015-1: as U5 on sheet Regulator
U7 = CMP-0359-03372-2: Single Channel, Zero-Drift Operational Amplifier, 3 MHz Typical GBW, 2 V/us Typical SR, 2.7 to 11 V, 8-Pin SOIC (S8-8), Commercial, Pb-Free; Manufacturer: Linear Technology; GBW (MHz) Typical: 3; Vs Max (V): 11; Vos (mV) Typical: 0.0005; Is (mA) Typical: 0.8; Vs Min (V): 2.7; Channels (#): 1; SR (V/us) Typical: 2

## Sheet Support.SchDoc
size A3; SheetNumber: 4; SheetTotal: 5
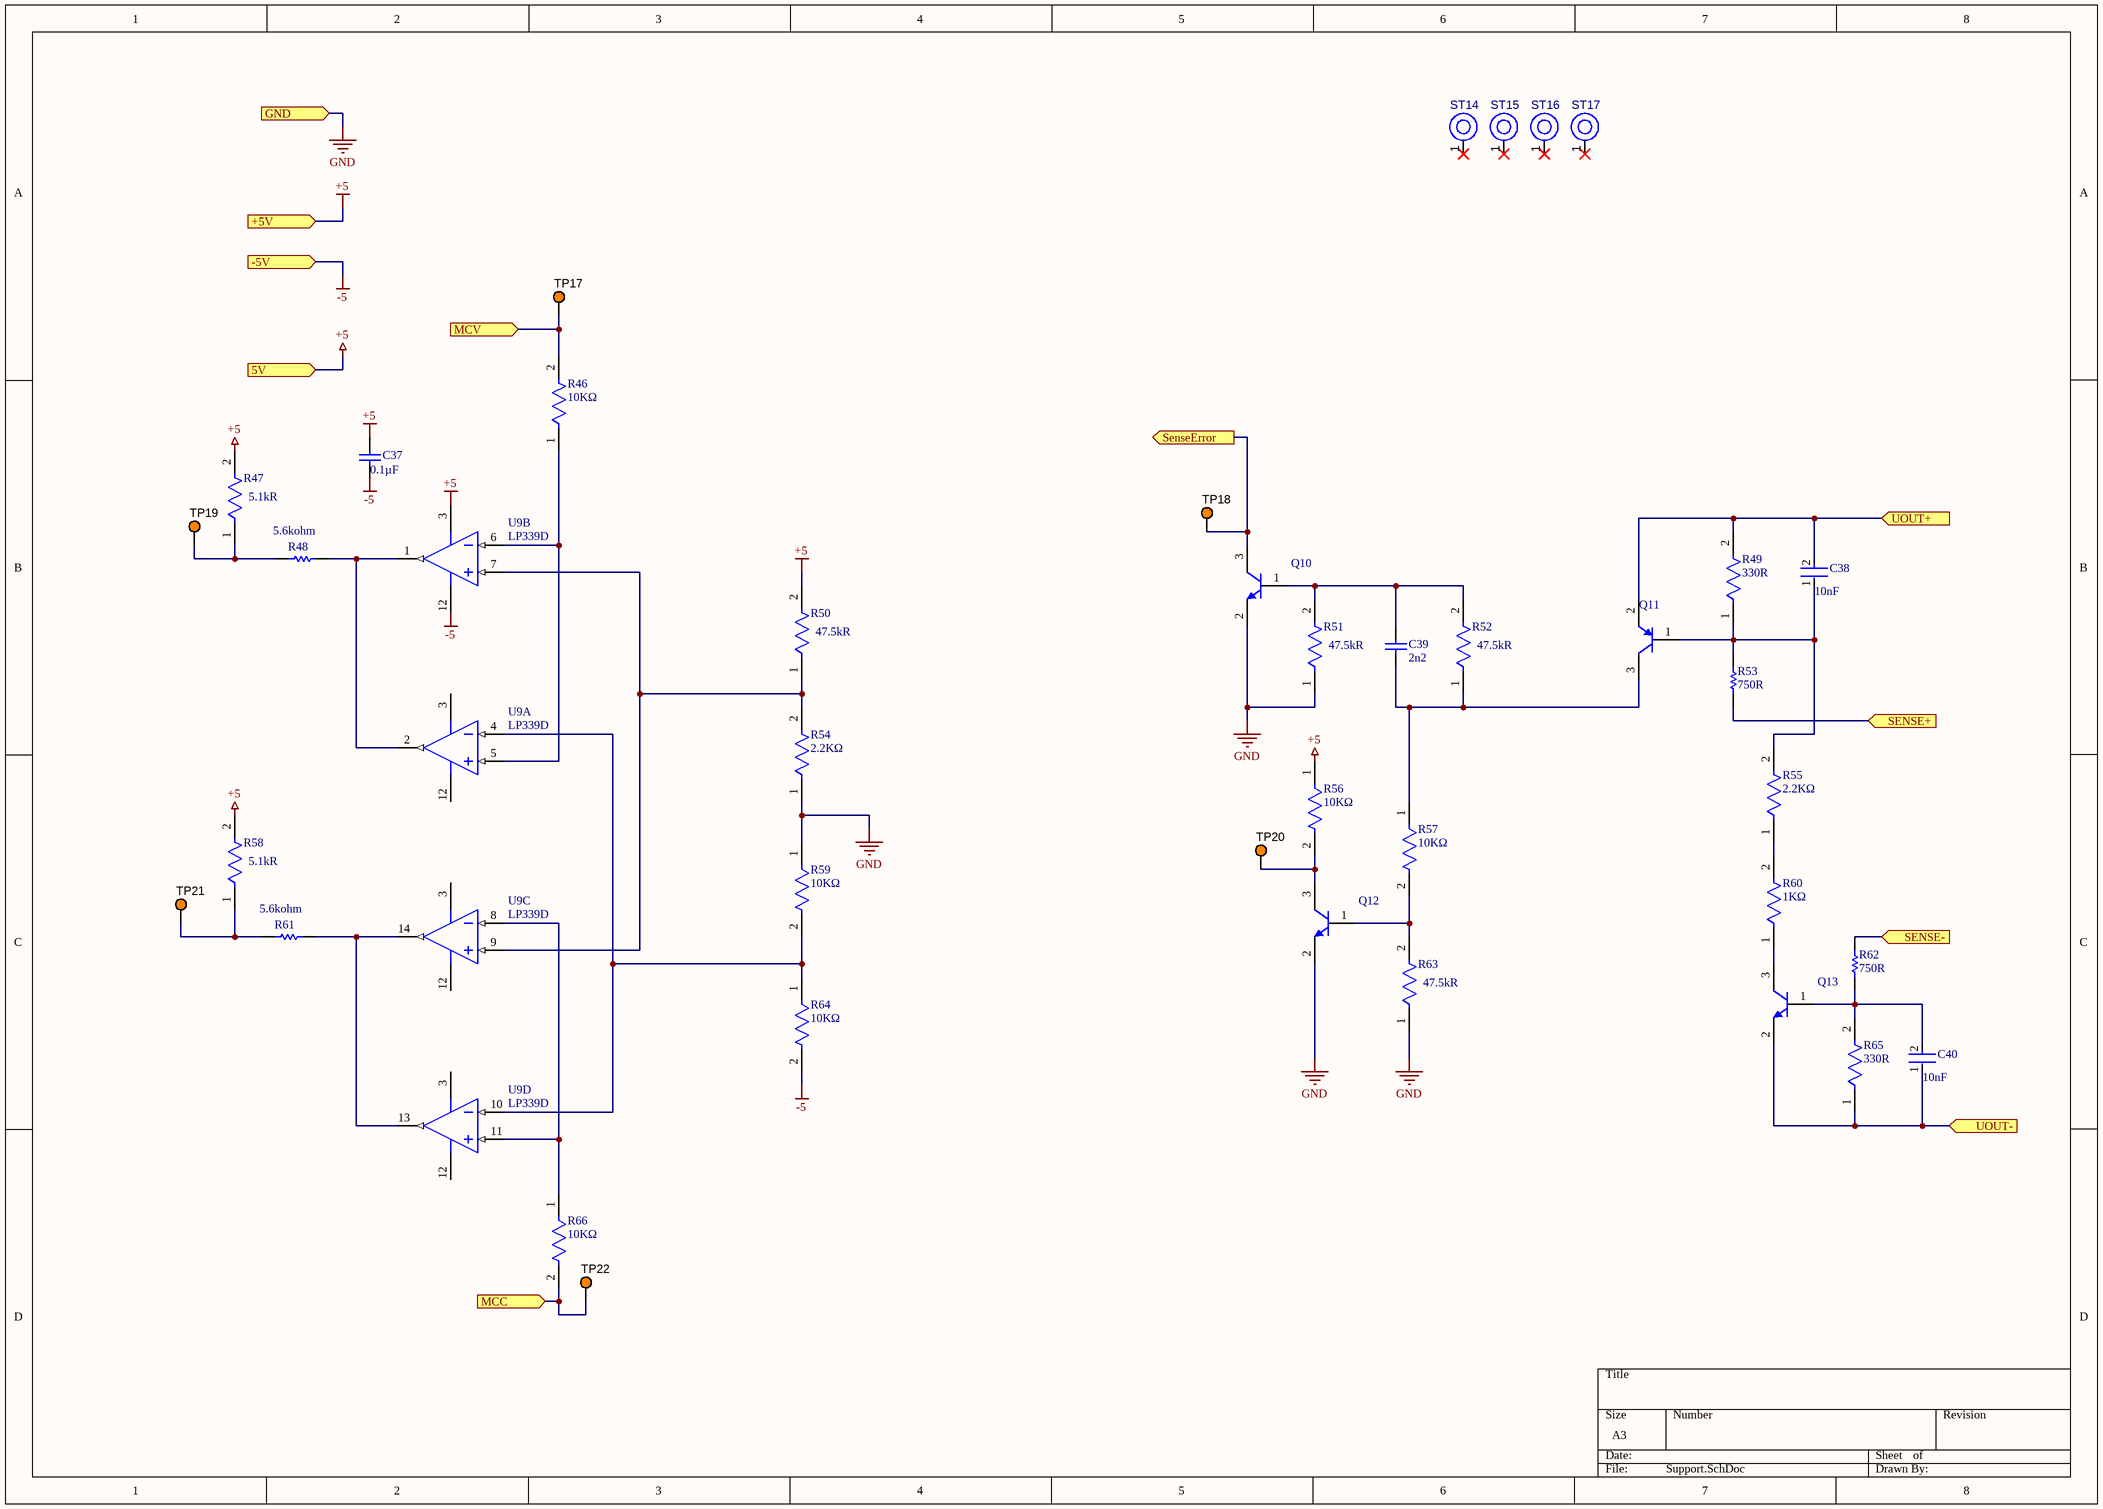
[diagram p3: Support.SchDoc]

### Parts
C37  Capacitance: 0.1µF  [SAMS-C0603-2_M]  (hidden comment: CL10B104KB8NNNC)
C38  Capacitance: 10nF  [FP-C1608-080-0_1-MFG]  (hidden comment: C1608X7R1H103M080AA)
C39  value 2n2  [CAPC1608X90X35ML15T15]  (hidden comment: 06035C222KAT4A)
C40  Capacitance: 10nF  [FP-C1608-080-0_1-MFG]  (hidden comment: C1608X7R1H103M080AA)
Q10  MMBT5551LT1G  [ONSC-SOT-23-3-318-08_V]  (value not drawn)
Q11  MMBT5401LT1G  [ONSC-SOT-23-3-318-08_V]  (value not drawn)
Q12  MMBT5551LT1G  [ONSC-SOT-23-3-318-08_V]  (value not drawn)
Q13  MMBT5551LT1G  [ONSC-SOT-23-3-318-08_V]  (value not drawn)
R46  Resistance: 10KΩ  [FP-RT0603-MFG]  (hidden comment: RT0603FRE0710KL)
R47  Resistance: 5.1kR  [FP-AC0603-MFG]  (hidden comment: AC0603FR-075K1L)
R48  Resistance: 5.6kohm  [RESC1608X55X25ML10T15]  (hidden comment: RC0603FR-075K6L)
R49  Resistance: 330R  [FP-CRCW0603-e3-MFG]  (hidden comment: CRCW0603330RFKEA)
R50  Resistance: 47.5kR  [FP-AC0603-MFG]  (hidden comment: AC0603FR-0747K5L)
R51  Resistance: 47.5kR  [FP-AC0603-MFG]  (hidden comment: AC0603FR-0747K5L)
R52  Resistance: 47.5kR  [FP-AC0603-MFG]  (hidden comment: AC0603FR-0747K5L)
R53  value 750R  [RESC1609X50X30ML10T20]  (hidden comment: CRCW0603750RJNEA)
R54  Resistance: 2.2KΩ  [FP-RT0603-MFG]  (hidden comment: RT0603BRD072K2L)
R55  Resistance: 2.2KΩ  [FP-RT0603-MFG]  (hidden comment: RT0603BRD072K2L)
R56  Resistance: 10KΩ  [FP-RT0603-MFG]  (hidden comment: RT0603FRE0710KL)
R57  Resistance: 10KΩ  [FP-RT0603-MFG]  (hidden comment: RT0603FRE0710KL)
R58  Resistance: 5.1kR  [FP-AC0603-MFG]  (hidden comment: AC0603FR-075K1L)
R59  Resistance: 10KΩ  [FP-RT0603-MFG]  (hidden comment: RT0603FRE0710KL)
R60  Resistance: 1KΩ  [FP-RT0603-MFG]  (hidden comment: RT0603FRE071KL)
R61  Resistance: 5.6kohm  [RESC1608X55X25ML10T15]  (hidden comment: RC0603FR-075K6L)
R62  value 750R  [RESC1609X50X30ML10T20]  (hidden comment: CRCW0603750RJNEA)
R63  Resistance: 47.5kR  [FP-AC0603-MFG]  (hidden comment: AC0603FR-0747K5L)
R64  Resistance: 10KΩ  [FP-RT0603-MFG]  (hidden comment: RT0603FRE0710KL)
R65  Resistance: 330R  [FP-CRCW0603-e3-MFG]  (hidden comment: CRCW0603330RFKEA)
R66  Resistance: 10KΩ  [FP-RT0603-MFG]  (hidden comment: RT0603FRE0710KL)
ST14  PTH-M2D5X5  [PTH-M2D5X5]  (value not drawn)
ST15  PTH-M2D5X5  [PTH-M2D5X5]  (value not drawn)
ST16  PTH-M2D5X5  [PTH-M2D5X5]  (value not drawn)
ST17  PTH-M2D5X5  [PTH-M2D5X5]  (value not drawn)
TP17  5003  [KSTN-5003]  (value not drawn)
TP18  5003  [KSTN-5003]  (value not drawn)
TP19  5003  [KSTN-5003]  (value not drawn)
TP20  5003  [KSTN-5003]  (value not drawn)
TP21  5003  [KSTN-5003]  (value not drawn)
TP22  5003  [KSTN-5003]  (value not drawn)
U9  LP339D  [D0014A_L]  (parts A,B,C,D of 4)

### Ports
5V (in, see PowerSupply[3A], Regulator[2D]), +5V (in, see ILoopAnd0.05V[2C], PowerSupply[4B], Regulator[2D]), -5V (in, see ILoopAnd0.05V[2C], PowerSupply[4C], Regulator[2D]), GND (in, see ILoopAnd0.05V[2C], PowerSupply[4B], Regulator[2C]), MCC (in, see ILoopAnd0.05V[2B]), MCV (in, see Regulator[5C]), SENSE+ (in, see Regulator[7B]), SENSE- (in, see Regulator[7C]), SenseError (out, see Regulator[3C]), UOUT+ (in, see Regulator[8A]), UOUT- (in, see ILoopAnd0.05V[7B], Regulator[8A])

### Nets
+5: C37.2 R47.2 R50.2 R56.1 R58.2 U9.3(V+) ; port +5V, port 5V
-5: C37.1 R64.2 U9.12(GND) ; port -5V
GND: Q10.2(E) Q12.2(E) R51.1 R54.1 R59.1 R63.1 ; port GND
SENSE+: R53.1 ; port SENSE+
SENSE-: R62.2 ; port SENSE-
UOUT+: C38.2 Q11.2(E) R49.2 ; port UOUT+
UOUT-: C40.1 Q13.2(E) R65.1 ; port UOUT-
NetC32_1: R66.2 TP22.1 ; port MCC
NetC38_1: C38.1 Q11.1(B) R49.1 R53.2 R55.2
NetC39_1: C39.1 Q11.3(C) R52.1 R57.1
NetC39_2: C39.2 Q10.1(B) R51.2 R52.2
NetC40_2: C40.2 Q13.1(B) R62.1 R65.2
NetD4_1: R46.2 TP17.1 ; port MCV
NetQ4_3: Q10.3(C) TP18.1 ; port SenseError
NetQ12_1: Q12.1(B) R57.2 R63.2
NetQ12_3: Q12.3(C) R56.2 TP20.1
NetQ13_3: Q13.3(C) R60.1
NetR46_1: R46.1 U9.5(IN1+) U9.6(IN2-)
NetR47_1: R47.1 R48.1 TP19.1
NetR48_2: R48.2 U9.1(OUT2) U9.2(OUT1)
NetR50_1: R50.1 R54.2 U9.7(IN2+) U9.9(IN3+)
NetR55_1: R55.1 R60.2
NetR58_1: R58.1 R61.1 TP21.1
NetR59_2: R59.2 R64.1 U9.4(IN1-) U9.10(IN4-)
NetR61_2: R61.2 U9.13(OUT4) U9.14(OUT3)
NetR66_1: R66.1 U9.8(IN3-) U9.11(IN4+)

Not connected (* = marked no-connect by the designer): ST14 1(H1)*; ST15 1(H1)*; ST16 1(H1)*; ST17 1(H1)*

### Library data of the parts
C37 = CMP-2000-05332-1: as C1 on sheet PowerSupply
C38 C40 = CMP-08246-006703-1: as C11 on sheet PowerSupply
C39 = CMP-2006-04410-1: Manufacturer: AVX Interconnect / Elco
Q10 Q12 Q13 = CMP-1048-00669-1: as Q5 on sheet Regulator
Q11 = CMP-1048-00557-1: as Q3 on sheet Regulator
R46 R56 R57 R59 R64 R66 = CMP-03412-005349-1: as R5 on sheet Regulator
R47 R58 = CMP-03412-025080-2: RES 5.1KΩ 1.00% 0.1W 0603; Voltage Rating: 50V; Temperature Coefficient: 100ppm/°C; Max Power Dissipation: 100mW; Tolerance: 1%
R48 R61 = CMP-1012-00595-2: Chip Resistor, 5.6 KOhm, +/- 1%, 0.1 W, -55 to 155 degC, 0603 (1608 Metric), RoHS, Tape and Reel; Voltage Rating: 50 V; Case\Package: 0603; Power Rating: 100 mW; Type (Resistor): Thick Film
R49 R65 = CMP-1012-00454-3: RES Thick Film, 330Ω, 1%, 0.1W, 100ppm/°C, 0603; Voltage Rating: 75V; Max Power Dissipation: 100mW
R50-R52 R63 = CMP-03412-027829-2: RES 47.5KΩ 1.00% 0.1W 0603; Tolerance: 1%; Temperature Coefficient: 100ppm/°C; Voltage Rating: 50V; Power Rating: 100mW
R53 R62 = CMP-2000-03570-1: Manufacturer: Vishay Dale
R54 R55 = CMP-2000-04423-2: as R23 on sheet Regulator
R60 = CMP-03412-005349-1: as R7 on sheet Regulator
ST14-ST17 = CMP-00028-00004-1: M2 PTH (2.5mm), 5mm pad
TP17-TP22 = CMP-002-00037-1: as TP1 on sheet PowerSupply
U9 = CMP-0055-00405-3: Ultra-Low Power Quad Comparator, 14-pin Narrow SOIC; Manufacturer: Texas Instruments; PackageTopMarking: NSUZXYTTE#*LP339M; CompType: Amplifiers; PowerWise: N

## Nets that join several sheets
0.05V: Regulator (R18.2), ILoopAnd0.05V (P2.2 R37.1)
+5: PowerSupply (FB1.2 FB3.2), Regulator (C23.2 C41.2 Q6.1 U5.8), ILoopAnd0.05V (6 pins), Support (6 pins)
-5: PowerSupply (FB4.2), Regulator (C23.1 C42.1 U5.4), ILoopAnd0.05V (6 pins), Support (C37.1 R64.2 U9.12)
GND: PowerSupply (28 pins), Regulator (16 pins), ILoopAnd0.05V (6 pins), Support (6 pins)
+REF2V5: PowerSupply (C15.2 C17.1 U4.2), Regulator (P1.1), ILoopAnd0.05V (P3.1 R35.2)
NetC1_2: PowerSupply (7 pins), Regulator (R10.1 ST10.1)
NetC32_1: ILoopAnd0.05V (5 pins), Support (R66.2 TP22.1)
NetD4_1: Regulator (5 pins), Support (R46.2 TP17.1)
NetD4_2: Regulator (D4.2 R20.1), ILoopAnd0.05V (D6.2)
NetQ4_3: Regulator (5 pins), Support (Q10.3 TP18.1)
SENSE+: Regulator (R16.2 R22.2 R23.1 TP23.1), Support (R53.1)
SENSE-: Regulator (R27.2 R28.1 R32.2 TP24.1), Support (R62.2)
UOUT+: Regulator (12 pins), Support (C38.2 Q11.2 R49.2)
UOUT-: Regulator (6 pins), ILoopAnd0.05V (C33.2 R.1 R40.2), Support (C40.1 Q13.2 R65.1)

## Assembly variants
Variant of MasterThesisRegulator: not fitted C? R? R? R?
